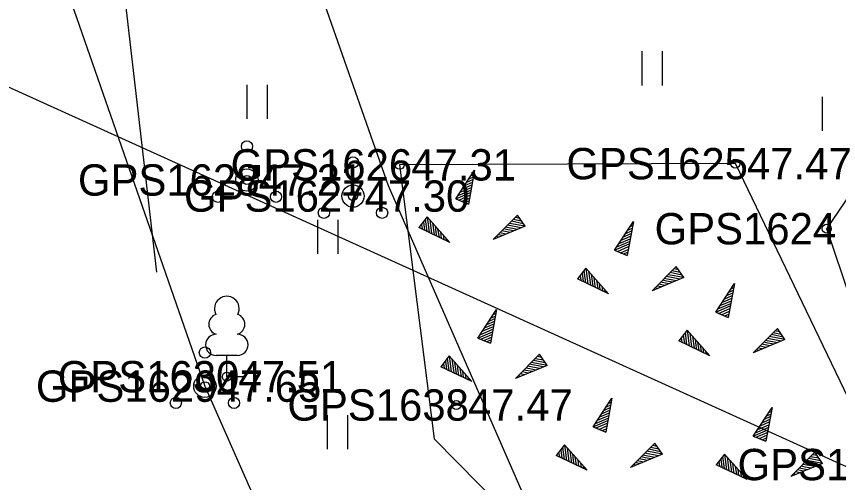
# Model space of a CAD drawing. Extents: x 551623 to 559850, y 6561220 to 6567135.
# Drawn here: x 555022.29 to 555040.68, y 6565623.09 to 6565633.51 of the extents above; entities that cross this region are included whole.
import ezdxf

# ---------------------------------------------------------------- set-up
doc = ezdxf.new("R2010")
doc.units = 0
for name, color, linetype in [('DTRASS', 7, 'Continuous'), ('HALJASTUS', 7, 'Continuous'), ('KORGUS-EH2000', 7, 'Continuous'), ('KPKAABEL', 7, 'Continuous'), ('MOOTKORG-EH2000', 7, 'Continuous'), ('MOOTMPUNKT', 7, 'Continuous'), ('MOOTNR', 7, 'Continuous'), ('MOOTPIIR', 7, 'Continuous'), ('PUU', 7, 'Continuous'), ('RELJEEF', 7, 'Continuous')]:
    doc.layers.add(name, color=color, linetype=linetype)

msp = doc.modelspace()

# ---------------------------------------------------------------- linework, layer by layer
at = {"layer": 'DTRASS'}
msp.add_line((555041.017, 6565623.369), (555014.503, 6565635.373), dxfattribs=at)
at = {"layer": 'HALJASTUS'}
for p, q in [((555036.276, 6565632.727), (555036.276, 6565631.965)), ((555036.731, 6565632.727), (555036.731, 6565631.965)), ((555027.445, 6565631.978), (555027.445, 6565631.217)), ((555027.9, 6565631.978), (555027.9, 6565631.217)), ((555040.315, 6565631.71), (555040.315, 6565630.949)), ((555029.028, 6565628.96), (555029.028, 6565628.199)), ((555029.483, 6565628.96), (555029.483, 6565628.199)), ((555029.243, 6565624.6), (555029.243, 6565623.839)), ((555029.698, 6565624.6), (555029.698, 6565623.839))]:
    msp.add_line(p, q, dxfattribs=at)
for points in [[(555015.748, 6565653.576), (555017.488, 6565651.124), (555020.222, 6565647.572), (555023.436, 6565640.122), (555024.391, 6565636.745), (555025.429, 6565627.792)], [(555057.023, 6565609.855), (555058.586, 6565605.616), (555058.613, 6565599.497), (555057.015, 6565597.532), (555043.839, 6565605.146), (555043.23, 6565610.761), (555037.198, 6565618.427), (555042.201, 6565623.493), (555040.415, 6565628.763), (555044.392, 6565634.613), (555048.032, 6565636.033)]]:
    msp.add_lwpolyline(points, dxfattribs=at)
at = {"layer": 'KORGUS-EH2000'}
for centre in [(555030.863, 6565630.19), (555040.415, 6565628.763), (555026.508, 6565625.245)]:
    msp.add_circle(centre, 0.1, dxfattribs=at)
at = {"layer": 'KPKAABEL'}
msp.add_lwpolyline([(555016.436, 6565669.854), (555020.596, 6565667.742), (555021.693, 6565667.12), (555022.688, 6565666.158), (555023.697, 6565665.37), (555024.08, 6565664.769), (555021.622, 6565652.627), (555021.526, 6565649.765), (555022.786, 6565647.231), (555026.485, 6565641.465), (555030.606, 6565629.728), (555035.378, 6565618.813), (555040.844, 6565608.057), (555047.089, 6565597.805), (555053.567, 6565587.292), (555056.073, 6565583.696), (555062.108, 6565572.667), (555068.248, 6565560.982)], dxfattribs=at)
at = {"layer": 'MOOTMPUNKT'}
for centre in [(555030.863, 6565630.19), (555038.371, 6565630.217), (555027.448, 6565629.851), (555029.819, 6565629.493), (555040.415, 6565628.763), (555026.998, 6565625.456), (555026.508, 6565625.245), (555032.132, 6565624.824)]:
    msp.add_circle(centre, 0.1, dxfattribs=at)
at = {"layer": 'MOOTPIIR'}
msp.add_lwpolyline([(555057.121, 6565656.605), (555043.846, 6565668.219), (555029.091, 6565671.127), (555021.803, 6565671.02), (555021.007, 6565667.338), (555020.786, 6565664.508), (555020.473, 6565663.799), (555017.828, 6565658.565), (555017.568, 6565657.887), (555016.649, 6565655.832), (555017.488, 6565651.124), (555026.508, 6565625.245), (555032.663, 6565611.321)], dxfattribs=at)
at = {"layer": 'PUU'}
for p, q in [((555027.238, 6565625.931), (555026.758, 6565625.931)), ((555026.998, 6565625.456), (555026.998, 6565625.931)), ((555027.378, 6565625.456), (555026.998, 6565625.456))]:
    msp.add_line(p, q, dxfattribs=at)
for centre, radius in [((555027.448, 6565630.601), 0.125), ((555029.819, 6565630.243), 0.125), ((555027.448, 6565629.851), 0.25), ((555026.798, 6565629.476), 0.125), ((555028.098, 6565629.476), 0.125), ((555029.819, 6565629.493), 0.25), ((555029.169, 6565629.118), 0.125), ((555030.47, 6565629.118), 0.125), ((555026.508, 6565625.995), 0.125), ((555026.508, 6565625.245), 0.25), ((555025.858, 6565624.87), 0.125), ((555027.159, 6565624.87), 0.125)]:
    msp.add_circle(centre, radius, dxfattribs=at)
for centre, radius, start, end in [((555026.998, 6565626.976), 0.277, 332.5799, 207.4201), ((555026.828, 6565626.628), 0.233, 109.0217, 253.1415), ((555027.168, 6565626.628), 0.233, 286.8508, 70.9859), ((555026.76, 6565626.168), 0.238, 90.0016, 269.3953), ((555027.235, 6565626.168), 0.238, 270.6047, 89.9984)]:
    msp.add_arc(centre, radius, start, end, dxfattribs=at)
at = {"layer": 'RELJEEF'}
for p, q in [((555032.119, 6565629.429), (555032.539, 6565630.069)), ((555032.539, 6565630.069), (555032.399, 6565629.314)), ((555032.464, 6565629.954), (555032.524, 6565629.979)), ((555032.514, 6565630.029), (555032.534, 6565630.039)), ((555032.319, 6565629.729), (555032.489, 6565629.804)), ((555032.369, 6565629.804), (555032.499, 6565629.864)), ((555032.414, 6565629.879), (555032.514, 6565629.919)), ((555032.169, 6565629.504), (555032.454, 6565629.624)), ((555032.219, 6565629.579), (555032.469, 6565629.684)), ((555032.269, 6565629.654), (555032.394, 6565629.709)), ((555032.394, 6565629.709), (555032.479, 6565629.744)), ((555032.119, 6565629.429), (555032.444, 6565629.569)), ((555032.119, 6565629.429), (555032.399, 6565629.314)), ((555032.119, 6565629.429), (555032.119, 6565629.429)), ((555032.184, 6565629.404), (555032.434, 6565629.509)), ((555032.249, 6565629.374), (555032.424, 6565629.449)), ((555032.319, 6565629.349), (555032.414, 6565629.389)), ((555032.384, 6565629.324), (555032.399, 6565629.329)), ((555032.957, 6565628.523), (555033.497, 6565629.068)), ((555033.507, 6565629.053), (555033.487, 6565629.053)), ((555033.667, 6565628.818), (555033.497, 6565629.068)), ((555031.478, 6565629.028), (555031.293, 6565628.788)), ((555031.348, 6565628.858), (555031.363, 6565628.758)), ((555031.393, 6565628.918), (555031.418, 6565628.733)), ((555031.433, 6565628.973), (555031.468, 6565628.703)), ((555031.478, 6565629.028), (555031.983, 6565628.458)), ((555031.478, 6565629.028), (555031.523, 6565628.678)), ((555031.478, 6565629.028), (555031.478, 6565629.028)), ((555031.538, 6565628.963), (555031.578, 6565628.653)), ((555031.598, 6565628.893), (555031.633, 6565628.628)), ((555033.667, 6565628.818), (555033.317, 6565628.883)), ((555033.627, 6565628.873), (555033.362, 6565628.928)), ((555033.587, 6565628.933), (555033.402, 6565628.968)), ((555033.547, 6565628.993), (555033.447, 6565629.013)), ((555035.669, 6565628.282), (555036.089, 6565628.922)), ((555036.089, 6565628.922), (555035.949, 6565628.167)), ((555036.064, 6565628.882), (555036.084, 6565628.892)), ((555031.983, 6565628.458), (555031.293, 6565628.788)), ((555031.303, 6565628.803), (555031.308, 6565628.783)), ((555031.658, 6565628.828), (555031.673, 6565628.688)), ((555031.673, 6565628.688), (555031.688, 6565628.598)), ((555031.713, 6565628.758), (555031.743, 6565628.573)), ((555031.773, 6565628.693), (555031.793, 6565628.548)), ((555033.667, 6565628.818), (555032.957, 6565628.523)), ((555033.247, 6565628.643), (555033.107, 6565628.673)), ((555033.332, 6565628.678), (555033.147, 6565628.713)), ((555033.282, 6565628.738), (555033.192, 6565628.758)), ((555033.497, 6565628.748), (555033.232, 6565628.798)), ((555033.582, 6565628.783), (555033.277, 6565628.843)), ((555033.417, 6565628.713), (555033.282, 6565628.738)), ((555033.667, 6565628.818), (555033.667, 6565628.818)), ((555035.919, 6565628.657), (555036.049, 6565628.717)), ((555035.964, 6565628.732), (555036.064, 6565628.772)), ((555036.014, 6565628.807), (555036.074, 6565628.832)), ((555031.833, 6565628.623), (555031.848, 6565628.523)), ((555031.893, 6565628.558), (555031.903, 6565628.493)), ((555031.953, 6565628.488), (555031.958, 6565628.468)), ((555032.997, 6565628.538), (555032.982, 6565628.543)), ((555033.082, 6565628.573), (555033.022, 6565628.588)), ((555033.167, 6565628.608), (555033.062, 6565628.628)), ((555035.769, 6565628.432), (555036.019, 6565628.537)), ((555035.819, 6565628.507), (555035.944, 6565628.562)), ((555035.869, 6565628.582), (555036.039, 6565628.657)), ((555035.944, 6565628.562), (555036.029, 6565628.597)), ((555035.669, 6565628.282), (555035.994, 6565628.422)), ((555035.719, 6565628.357), (555036.004, 6565628.477)), ((555035.734, 6565628.257), (555035.984, 6565628.362)), ((555035.669, 6565628.282), (555035.949, 6565628.167)), ((555035.669, 6565628.282), (555035.669, 6565628.282)), ((555035.799, 6565628.227), (555035.974, 6565628.302)), ((555035.869, 6565628.202), (555035.964, 6565628.242)), ((555035.934, 6565628.177), (555035.949, 6565628.182)), ((555035.028, 6565627.881), (555034.843, 6565627.641)), ((555034.943, 6565627.771), (555034.968, 6565627.586)), ((555034.983, 6565627.826), (555035.018, 6565627.556)), ((555035.028, 6565627.881), (555035.533, 6565627.311)), ((555035.028, 6565627.881), (555035.073, 6565627.531)), ((555035.028, 6565627.881), (555035.028, 6565627.881)), ((555035.088, 6565627.816), (555035.128, 6565627.506)), ((555036.507, 6565627.376), (555037.047, 6565627.921)), ((555037.177, 6565627.726), (555036.912, 6565627.781)), ((555037.137, 6565627.786), (555036.952, 6565627.821)), ((555037.097, 6565627.846), (555036.997, 6565627.866)), ((555037.057, 6565627.906), (555037.037, 6565627.906)), ((555037.217, 6565627.671), (555037.047, 6565627.921)), ((555035.533, 6565627.311), (555034.843, 6565627.641)), ((555034.853, 6565627.656), (555034.858, 6565627.636)), ((555034.898, 6565627.711), (555034.913, 6565627.611)), ((555035.148, 6565627.746), (555035.183, 6565627.481)), ((555035.208, 6565627.681), (555035.223, 6565627.541)), ((555035.263, 6565627.611), (555035.293, 6565627.426)), ((555037.217, 6565627.671), (555036.507, 6565627.376)), ((555036.832, 6565627.591), (555036.742, 6565627.611)), ((555037.047, 6565627.601), (555036.782, 6565627.651)), ((555037.132, 6565627.636), (555036.827, 6565627.696)), ((555036.967, 6565627.566), (555036.832, 6565627.591)), ((555037.217, 6565627.671), (555036.867, 6565627.736)), ((555037.217, 6565627.671), (555037.217, 6565627.671)), ((555035.223, 6565627.541), (555035.238, 6565627.451)), ((555035.323, 6565627.546), (555035.343, 6565627.401)), ((555035.383, 6565627.476), (555035.398, 6565627.376)), ((555035.443, 6565627.411), (555035.453, 6565627.346)), ((555036.547, 6565627.391), (555036.532, 6565627.396)), ((555036.632, 6565627.426), (555036.572, 6565627.441)), ((555036.717, 6565627.461), (555036.612, 6565627.481)), ((555036.797, 6565627.496), (555036.657, 6565627.526)), ((555036.882, 6565627.531), (555036.697, 6565627.566)), ((555037.932, 6565626.897), (555038.352, 6565627.537)), ((555038.352, 6565627.537), (555038.212, 6565626.782)), ((555038.227, 6565627.347), (555038.327, 6565627.387)), ((555038.277, 6565627.422), (555038.337, 6565627.447)), ((555038.327, 6565627.497), (555038.347, 6565627.507)), ((555035.503, 6565627.341), (555035.508, 6565627.321)), ((555038.132, 6565627.197), (555038.302, 6565627.272)), ((555038.182, 6565627.272), (555038.312, 6565627.332)), ((555038.207, 6565627.177), (555038.292, 6565627.212)), ((555037.932, 6565626.897), (555038.257, 6565627.037)), ((555037.982, 6565626.972), (555038.267, 6565627.092)), ((555038.032, 6565627.047), (555038.282, 6565627.152)), ((555038.082, 6565627.122), (555038.207, 6565627.177)), ((555032.612, 6565626.32), (555033.032, 6565626.96)), ((555033.032, 6565626.96), (555032.892, 6565626.205)), ((555032.957, 6565626.845), (555033.017, 6565626.87)), ((555033.007, 6565626.92), (555033.027, 6565626.93)), ((555037.932, 6565626.897), (555038.212, 6565626.782)), ((555037.932, 6565626.897), (555037.932, 6565626.897)), ((555037.997, 6565626.872), (555038.247, 6565626.977)), ((555038.062, 6565626.842), (555038.237, 6565626.917)), ((555038.132, 6565626.817), (555038.227, 6565626.857)), ((555032.812, 6565626.62), (555032.982, 6565626.695)), ((555032.862, 6565626.695), (555032.992, 6565626.755)), ((555032.907, 6565626.77), (555033.007, 6565626.81)), ((555038.197, 6565626.792), (555038.212, 6565626.797)), ((555032.662, 6565626.395), (555032.947, 6565626.515)), ((555032.712, 6565626.47), (555032.962, 6565626.575)), ((555032.762, 6565626.545), (555032.887, 6565626.6)), ((555032.887, 6565626.6), (555032.972, 6565626.635)), ((555037.291, 6565626.496), (555037.106, 6565626.256)), ((555037.291, 6565626.496), (555037.796, 6565625.926)), ((555037.291, 6565626.496), (555037.336, 6565626.146)), ((555037.291, 6565626.496), (555037.291, 6565626.496)), ((555038.77, 6565625.991), (555039.31, 6565626.536)), ((555039.36, 6565626.461), (555039.26, 6565626.481)), ((555039.32, 6565626.521), (555039.3, 6565626.521)), ((555039.48, 6565626.286), (555039.31, 6565626.536)), ((555032.612, 6565626.32), (555032.937, 6565626.46)), ((555032.612, 6565626.32), (555032.892, 6565626.205)), ((555032.612, 6565626.32), (555032.612, 6565626.32)), ((555032.677, 6565626.295), (555032.927, 6565626.4)), ((555032.742, 6565626.265), (555032.917, 6565626.34)), ((555037.161, 6565626.326), (555037.176, 6565626.226)), ((555037.206, 6565626.386), (555037.231, 6565626.201)), ((555037.246, 6565626.441), (555037.281, 6565626.171)), ((555037.351, 6565626.431), (555037.391, 6565626.121)), ((555037.411, 6565626.361), (555037.446, 6565626.096)), ((555037.471, 6565626.296), (555037.486, 6565626.156)), ((555039.48, 6565626.286), (555038.77, 6565625.991)), ((555039.395, 6565626.251), (555039.09, 6565626.311)), ((555039.48, 6565626.286), (555039.13, 6565626.351)), ((555039.44, 6565626.341), (555039.175, 6565626.396)), ((555039.4, 6565626.401), (555039.215, 6565626.436)), ((555039.48, 6565626.286), (555039.48, 6565626.286)), ((555032.812, 6565626.24), (555032.907, 6565626.28)), ((555032.877, 6565626.215), (555032.892, 6565626.22)), ((555037.796, 6565625.926), (555037.106, 6565626.256)), ((555037.116, 6565626.271), (555037.121, 6565626.251)), ((555037.486, 6565626.156), (555037.501, 6565626.066)), ((555037.526, 6565626.226), (555037.556, 6565626.041)), ((555037.586, 6565626.161), (555037.606, 6565626.016)), ((555039.06, 6565626.111), (555038.92, 6565626.141)), ((555039.145, 6565626.146), (555038.96, 6565626.181)), ((555039.095, 6565626.206), (555039.005, 6565626.226)), ((555039.31, 6565626.216), (555039.045, 6565626.266)), ((555039.23, 6565626.181), (555039.095, 6565626.206)), ((555031.971, 6565625.919), (555031.786, 6565625.679)), ((555031.971, 6565625.919), (555032.476, 6565625.349)), ((555031.971, 6565625.919), (555032.016, 6565625.569)), ((555031.971, 6565625.919), (555031.971, 6565625.919)), ((555033.45, 6565625.414), (555033.99, 6565625.959)), ((555034, 6565625.944), (555033.98, 6565625.944)), ((555034.16, 6565625.709), (555033.99, 6565625.959)), ((555037.646, 6565626.091), (555037.661, 6565625.991)), ((555037.706, 6565626.026), (555037.716, 6565625.961)), ((555037.766, 6565625.956), (555037.771, 6565625.936)), ((555038.81, 6565626.006), (555038.795, 6565626.011)), ((555038.895, 6565626.041), (555038.835, 6565626.056)), ((555038.98, 6565626.076), (555038.875, 6565626.096)), ((555031.841, 6565625.749), (555031.856, 6565625.649)), ((555031.886, 6565625.809), (555031.911, 6565625.624)), ((555031.926, 6565625.864), (555031.961, 6565625.594)), ((555032.031, 6565625.854), (555032.071, 6565625.544)), ((555032.091, 6565625.784), (555032.126, 6565625.519)), ((555034.075, 6565625.674), (555033.77, 6565625.734)), ((555034.16, 6565625.709), (555033.81, 6565625.774)), ((555034.12, 6565625.764), (555033.855, 6565625.819)), ((555034.08, 6565625.824), (555033.895, 6565625.859)), ((555034.04, 6565625.884), (555033.94, 6565625.904)), ((555032.476, 6565625.349), (555031.786, 6565625.679)), ((555031.796, 6565625.694), (555031.801, 6565625.674)), ((555032.151, 6565625.719), (555032.166, 6565625.579)), ((555032.166, 6565625.579), (555032.181, 6565625.489)), ((555032.206, 6565625.649), (555032.236, 6565625.464)), ((555032.266, 6565625.584), (555032.286, 6565625.439)), ((555034.16, 6565625.709), (555033.45, 6565625.414)), ((555033.74, 6565625.534), (555033.6, 6565625.564)), ((555033.825, 6565625.569), (555033.64, 6565625.604)), ((555033.775, 6565625.629), (555033.685, 6565625.649)), ((555033.99, 6565625.639), (555033.725, 6565625.689)), ((555033.91, 6565625.604), (555033.775, 6565625.629)), ((555034.16, 6565625.709), (555034.16, 6565625.709)), ((555032.326, 6565625.514), (555032.341, 6565625.414)), ((555032.386, 6565625.449), (555032.396, 6565625.384)), ((555032.446, 6565625.379), (555032.451, 6565625.359)), ((555033.49, 6565625.429), (555033.475, 6565625.434)), ((555033.575, 6565625.464), (555033.515, 6565625.479)), ((555033.66, 6565625.499), (555033.555, 6565625.519)), ((555035.191, 6565624.335), (555035.611, 6565624.975)), ((555035.611, 6565624.975), (555035.471, 6565624.22)), ((555035.486, 6565624.785), (555035.586, 6565624.825)), ((555035.536, 6565624.86), (555035.596, 6565624.885)), ((555035.586, 6565624.935), (555035.606, 6565624.945)), ((555035.391, 6565624.635), (555035.561, 6565624.71)), ((555035.441, 6565624.71), (555035.571, 6565624.77)), ((555035.466, 6565624.615), (555035.551, 6565624.65)), ((555038.77, 6565624.129), (555039.19, 6565624.769)), ((555039.19, 6565624.769), (555039.05, 6565624.014)), ((555039.115, 6565624.654), (555039.175, 6565624.679)), ((555039.165, 6565624.729), (555039.185, 6565624.739)), ((555035.191, 6565624.335), (555035.516, 6565624.475)), ((555035.241, 6565624.41), (555035.526, 6565624.53)), ((555035.291, 6565624.485), (555035.541, 6565624.59)), ((555035.341, 6565624.56), (555035.466, 6565624.615)), ((555038.97, 6565624.429), (555039.14, 6565624.504)), ((555039.02, 6565624.504), (555039.15, 6565624.564)), ((555039.045, 6565624.409), (555039.13, 6565624.444)), ((555039.065, 6565624.579), (555039.165, 6565624.619)), ((555035.191, 6565624.335), (555035.471, 6565624.22)), ((555035.191, 6565624.335), (555035.191, 6565624.335)), ((555035.256, 6565624.31), (555035.506, 6565624.415)), ((555035.321, 6565624.28), (555035.496, 6565624.355)), ((555035.391, 6565624.255), (555035.486, 6565624.295)), ((555038.77, 6565624.129), (555039.095, 6565624.269)), ((555038.82, 6565624.204), (555039.105, 6565624.324)), ((555038.87, 6565624.279), (555039.12, 6565624.384)), ((555038.92, 6565624.354), (555039.045, 6565624.409)), ((555035.456, 6565624.23), (555035.471, 6565624.235)), ((555038.77, 6565624.129), (555039.05, 6565624.014)), ((555038.77, 6565624.129), (555038.77, 6565624.129)), ((555038.835, 6565624.104), (555039.085, 6565624.209)), ((555038.9, 6565624.074), (555039.075, 6565624.149)), ((555038.97, 6565624.049), (555039.065, 6565624.089)), ((555034.549, 6565623.934), (555034.364, 6565623.694)), ((555034.549, 6565623.934), (555035.054, 6565623.364)), ((555034.549, 6565623.934), (555034.594, 6565623.584)), ((555034.549, 6565623.934), (555034.549, 6565623.934)), ((555036.029, 6565623.429), (555036.569, 6565623.974)), ((555036.619, 6565623.899), (555036.519, 6565623.919)), ((555036.579, 6565623.959), (555036.559, 6565623.959)), ((555036.739, 6565623.724), (555036.569, 6565623.974)), ((555039.035, 6565624.024), (555039.05, 6565624.029)), ((555034.374, 6565623.709), (555034.379, 6565623.689)), ((555034.419, 6565623.764), (555034.434, 6565623.664)), ((555034.464, 6565623.824), (555034.489, 6565623.639)), ((555034.504, 6565623.879), (555034.539, 6565623.609)), ((555034.609, 6565623.869), (555034.649, 6565623.559)), ((555034.669, 6565623.799), (555034.704, 6565623.534)), ((555034.729, 6565623.734), (555034.744, 6565623.594)), ((555036.739, 6565623.724), (555036.029, 6565623.429)), ((555036.654, 6565623.689), (555036.349, 6565623.749)), ((555036.739, 6565623.724), (555036.389, 6565623.789)), ((555036.699, 6565623.779), (555036.434, 6565623.834)), ((555036.659, 6565623.839), (555036.474, 6565623.874)), ((555036.739, 6565623.724), (555036.739, 6565623.724)), ((555038.128, 6565623.728), (555037.943, 6565623.488)), ((555038.128, 6565623.728), (555038.633, 6565623.158)), ((555038.128, 6565623.728), (555038.173, 6565623.378)), ((555038.128, 6565623.728), (555038.128, 6565623.728)), ((555039.608, 6565623.223), (555040.148, 6565623.768)), ((555040.198, 6565623.693), (555040.098, 6565623.713)), ((555040.158, 6565623.753), (555040.138, 6565623.753)), ((555040.318, 6565623.518), (555040.148, 6565623.768)), ((555035.054, 6565623.364), (555034.364, 6565623.694)), ((555034.744, 6565623.594), (555034.759, 6565623.504)), ((555034.784, 6565623.664), (555034.814, 6565623.479)), ((555034.844, 6565623.599), (555034.864, 6565623.454)), ((555034.904, 6565623.529), (555034.919, 6565623.429)), ((555036.239, 6565623.514), (555036.134, 6565623.534)), ((555036.319, 6565623.549), (555036.179, 6565623.579)), ((555036.404, 6565623.584), (555036.219, 6565623.619)), ((555036.354, 6565623.644), (555036.264, 6565623.664)), ((555036.569, 6565623.654), (555036.304, 6565623.704)), ((555036.489, 6565623.619), (555036.354, 6565623.644)), ((555037.998, 6565623.558), (555038.013, 6565623.458)), ((555038.043, 6565623.618), (555038.068, 6565623.433)), ((555038.083, 6565623.673), (555038.118, 6565623.403)), ((555038.188, 6565623.663), (555038.228, 6565623.353)), ((555038.248, 6565623.593), (555038.283, 6565623.328)), ((555038.308, 6565623.528), (555038.323, 6565623.388)), ((555040.233, 6565623.483), (555039.928, 6565623.543)), ((555040.318, 6565623.518), (555039.968, 6565623.583)), ((555040.278, 6565623.573), (555040.013, 6565623.628)), ((555040.238, 6565623.633), (555040.053, 6565623.668)), ((555034.964, 6565623.464), (555034.974, 6565623.399)), ((555035.024, 6565623.394), (555035.029, 6565623.374)), ((555036.069, 6565623.444), (555036.054, 6565623.449)), ((555036.154, 6565623.479), (555036.094, 6565623.494)), ((555038.633, 6565623.158), (555037.943, 6565623.488)), ((555037.953, 6565623.503), (555037.958, 6565623.483)), ((555038.323, 6565623.388), (555038.338, 6565623.298)), ((555038.363, 6565623.458), (555038.393, 6565623.273)), ((555038.423, 6565623.393), (555038.443, 6565623.248)), ((555040.318, 6565623.518), (555039.608, 6565623.223)), ((555039.898, 6565623.343), (555039.758, 6565623.373)), ((555039.983, 6565623.378), (555039.798, 6565623.413)), ((555039.933, 6565623.438), (555039.843, 6565623.458)), ((555040.148, 6565623.448), (555039.883, 6565623.498)), ((555040.068, 6565623.413), (555039.933, 6565623.438)), ((555040.318, 6565623.518), (555040.318, 6565623.518)), ((555038.483, 6565623.323), (555038.498, 6565623.223)), ((555038.543, 6565623.258), (555038.553, 6565623.193)), ((555038.603, 6565623.188), (555038.608, 6565623.168)), ((555039.648, 6565623.238), (555039.633, 6565623.243)), ((555039.733, 6565623.273), (555039.673, 6565623.288)), ((555039.818, 6565623.308), (555039.713, 6565623.328))]:
    msp.add_line(p, q, dxfattribs=at)
msp.add_lwpolyline([(555030.863, 6565630.19), (555031.632, 6565624.071), (555037.198, 6565618.427), (555040.417, 6565618.809), (555041.648, 6565623.42), (555038.371, 6565630.217)], close=True, dxfattribs=at)

# ---------------------------------------------------------------- texts
at = {"layer": 'KORGUS-EH2000'}
for s, p in [(' 47.31', (555030.863, 6565629.84)), (' 47.65', (555026.508, 6565624.895))]:
    msp.add_text(s, height=0.7, dxfattribs=at).set_placement(p)
at = {"layer": 'MOOTKORG-EH2000'}
for s, p in [(' 47.31', (555030.863, 6565629.84)), (' 47.47', (555038.371, 6565629.867)), (' 47.21', (555027.448, 6565629.502)), (' 47.30', (555029.819, 6565629.143)), (' 47.51', (555026.998, 6565625.106)), (' 47.65', (555026.508, 6565624.895)), (' 47.47', (555032.132, 6565624.474))]:
    msp.add_text(s, height=0.7, dxfattribs=at).set_placement(p)
at = {"layer": 'MOOTNR'}
for s, p in [('GPS1626 ', (555027.083, 6565629.84)), ('GPS1625 ', (555034.592, 6565629.867)), ('GPS1628 ', (555023.669, 6565629.502)), ('GPS1627 ', (555026.04, 6565629.143)), ('GPS1624 ', (555036.565, 6565628.413)), ('GPS1630 ', (555023.218, 6565625.106)), ('GPS1629 ', (555022.729, 6565624.895)), ('GPS1638 ', (555028.352, 6565624.474)), ('GPS1623 ', (555038.421, 6565623.143))]:
    msp.add_text(s, height=0.7, dxfattribs=at).set_placement(p)

doc.saveas('drawing.dxf')
